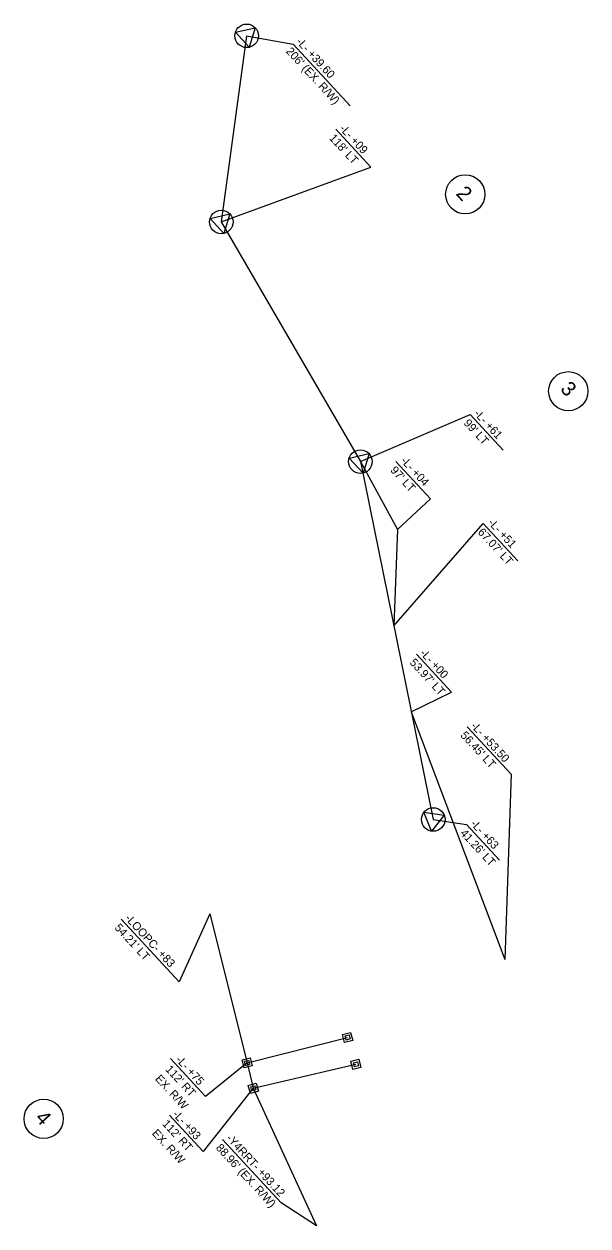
# Model space of a CAD drawing. Extents: x 1703100 to 1704058, y 794243 to 795715.
# Drawn here: x 1703714 to 1704058, y 794243 to 794978 of the extents above; entities that cross this region are included whole.
import ezdxf

# ---------------------------------------------------------------- set-up
doc = ezdxf.new("R2010")
doc.units = 0
for name, color, linetype in [('Prop Easement Construction', 7, 'Continuous'), ('Prop Easement Construction Station Offsets', 7, 'Continuous'), ('Prop Easement Permanent Drainage', 7, 'Continuous'), ('Prop Easement Permanent Drainage Station Offsets', 7, 'Continuous'), ('Prop Easement Temporary Drainage', 7, 'Continuous'), ('Prop Easement Temporary Drainage Station Offsets', 7, 'Continuous'), ('Prop Parcel Number CELL', 7, 'Continuous'), ('Prop Parcel Number Text', 7, 'Continuous'), ('Prop ROW Marker CELL', 7, 'Continuous'), ('Prop ROW Permanent Easement CELL', 7, 'Continuous'), ('Prop ROW RW Lines', 7, 'Continuous'), ('Prop ROW Station Offsets', 7, 'Continuous')]:
    doc.layers.add(name, color=color, linetype=linetype)

msp = doc.modelspace()

# ---------------------------------------------------------------- linework, layer by layer
at = {"layer": 'Prop Easement Construction'}
for p, q in [((1703950.31, 794557.04), (1704007.51, 794405.65)), ((1703827.17, 794433.6), (1703850, 794342.38)), ((1703853.78, 794326.85), (1703892.47, 794242.67))]:
    msp.add_line(p, q, dxfattribs=at)
at = {"layer": 'Prop Easement Construction Station Offsets'}
for p, q in [((1703953.44, 794592.3), (1703974.97, 794568.98)), ((1703950.31, 794557.04), (1703974.97, 794568.98)), ((1703984.48, 794547.84), (1704011.25, 794518.83)), ((1704011.25, 794518.83), (1704007.51, 794405.65)), ((1703827.17, 794433.6), (1703808.47, 794391.95)), ((1703773.14, 794430.21), (1703808.47, 794391.95)), ((1703835.01, 794295.6), (1703870.79, 794256.84)), ((1703892.47, 794242.67), (1703870.79, 794256.84))]:
    msp.add_line(p, q, dxfattribs=at)
at = {"layer": 'Prop Easement Permanent Drainage'}
for p, q in [((1703850, 794342.38), (1703911.4, 794357.91)), ((1703850, 794342.38), (1703853.78, 794326.85)), ((1703853.78, 794326.85), (1703916.46, 794341.51))]:
    msp.add_line(p, q, dxfattribs=at)
at = {"layer": 'Prop Easement Permanent Drainage Station Offsets'}
for p, q in [((1703803.25, 794345), (1703824.56, 794321.92)), ((1703850, 794342.38), (1703824.56, 794321.92)), ((1703853.78, 794326.85), (1703823.09, 794288.17)), ((1703802.49, 794310.49), (1703823.09, 794288.17))]:
    msp.add_line(p, q, dxfattribs=at)
at = {"layer": 'Prop Easement Temporary Drainage'}
for p, q in [((1703919.23, 794710.03), (1703941.8, 794668.51)), ((1703941.8, 794668.51), (1703939.64, 794609.55))]:
    msp.add_line(p, q, dxfattribs=at)
at = {"layer": 'Prop Easement Temporary Drainage Station Offsets'}
for p, q in [((1703962.01, 794687.16), (1703940.79, 794710.15)), ((1703941.8, 794668.51), (1703962.01, 794687.16)), ((1703939.64, 794609.55), (1703994.15, 794672.27)), ((1704015.37, 794649.28), (1703994.15, 794672.27))]:
    msp.add_line(p, q, dxfattribs=at)
at = {"layer": 'Prop Parcel Number CELL'}
for p, q in [((1703983.3, 794873.43), (1703983.3, 794873.43)), ((1704046.26, 794753.04), (1704046.26, 794753.04)), ((1703725.7, 794308.16), (1703725.7, 794308.16))]:
    msp.add_line(p, q, dxfattribs=at)
for centre in [(1703983.3, 794873.43), (1704046.26, 794753.04), (1703725.7, 794308.16)]:
    msp.add_circle(centre, 12, dxfattribs=at)
at = {"layer": 'Prop ROW Marker CELL'}
for p, q in [((1703849.71, 794970.36), (1703849.71, 794970.36)), ((1703834.24, 794856.55), (1703834.24, 794856.55)), ((1703919.23, 794710.03), (1703919.23, 794710.03)), ((1703963.72, 794491.19), (1703963.72, 794491.19))]:
    msp.add_line(p, q, dxfattribs=at)
for points in [[(1703842.82, 794972.51), (1703855, 794975.24), (1703851.3, 794963.32)], [(1703827.35, 794858.7), (1703839.53, 794861.43), (1703835.83, 794849.52)], [(1703912.35, 794712.18), (1703924.52, 794714.91), (1703920.83, 794702.99)], [(1703958.06, 794495.65), (1703970.4, 794493.86), (1703962.7, 794484.05)]]:
    msp.add_lwpolyline(points, close=True, dxfattribs=at)
for centre in [(1703849.71, 794970.36), (1703834.24, 794856.55), (1703919.23, 794710.03), (1703963.72, 794491.19)]:
    msp.add_circle(centre, 7.2, dxfattribs=at)
at = {"layer": 'Prop ROW Permanent Easement CELL'}
for p, q in [((1703911.41, 794357.91), (1703911.41, 794357.91)), ((1703850, 794342.38), (1703850, 794342.38)), ((1703916.46, 794341.51), (1703916.46, 794341.51)), ((1703853.78, 794326.85), (1703853.78, 794326.85))]:
    msp.add_line(p, q, dxfattribs=at)
for points in [[(1703914.51, 794356.09), (1703909.58, 794354.81), (1703908.3, 794359.74), (1703913.23, 794361.02)], [(1703912.96, 794357), (1703910.49, 794356.36), (1703909.85, 794358.83), (1703912.32, 794359.47)], [(1703851.89, 794345.45), (1703853.06, 794340.49), (1703848.11, 794339.32), (1703846.94, 794344.27)], [(1703850.95, 794343.92), (1703851.53, 794341.44), (1703849.06, 794340.85), (1703848.47, 794343.33)], [(1703919.55, 794339.66), (1703914.61, 794338.42), (1703913.37, 794343.36), (1703918.3, 794344.6)], [(1703918, 794340.59), (1703915.53, 794339.97), (1703914.91, 794342.43), (1703917.38, 794343.05)], [(1703850.64, 794328.62), (1703855.55, 794329.99), (1703856.92, 794325.09), (1703852.02, 794323.72)], [(1703852.21, 794327.74), (1703854.66, 794328.42), (1703855.35, 794325.97), (1703852.9, 794325.28)]]:
    msp.add_lwpolyline(points, close=True, dxfattribs=at)
at = {"layer": 'Prop ROW RW Lines'}
for points in [[(1703849.71, 794970.36), (1703834.24, 794856.55)], [(1703834.24, 794856.55), (1703919.23, 794710.03)], [(1703919.23, 794710.03), (1703963.72, 794491.19)]]:
    msp.add_lwpolyline(points, dxfattribs=at)
at = {"layer": 'Prop ROW Station Offsets'}
for p, q in [((1703849.71, 794970.36), (1703878.04, 794965.3)), ((1703878.04, 794965.3), (1703912.93, 794927.51)), ((1703925.62, 794890.03), (1703904.14, 794913.3)), ((1703834.24, 794856.55), (1703925.62, 794890.03)), ((1703919.23, 794710.03), (1703986.25, 794738.84)), ((1703986.25, 794738.84), (1704006.37, 794717.04)), ((1703963.72, 794491.19), (1703984.09, 794488.09)), ((1703984.09, 794488.09), (1704004.21, 794466.29))]:
    msp.add_line(p, q, dxfattribs=at)

# ---------------------------------------------------------------- texts
at = {"layer": 'Prop Easement Construction Station Offsets'}
for s, p in [("53.97' LT  ", (1703948.98, 794586.83)), ('-L- +00', (1703955.28, 794592.64)), ("56.45' LT  ", (1703980.02, 794542.36)), ('-L- +53.50', (1703986.32, 794548.18)), ("54.21' LT  ", (1703768.69, 794424.74)), ('-LOOPC- +83', (1703774.99, 794430.55)), ('-Y4RRT- +93.12', (1703836.86, 794295.94)), ("88.96' (EX. R/W) ", (1703830.56, 794290.13))]:
    msp.add_text(s, height=5, rotation=312.70907, dxfattribs=at).set_placement(p)
at = {"layer": 'Prop Easement Permanent Drainage Station Offsets'}
for s, p in [('-L- +75', (1703806.04, 794343.97)), ("112' RT", (1703799.75, 794338.15)), ('EX. R/W', (1703793.45, 794332.34)), ('-L- +93', (1703804.12, 794310.64)), ('EX. R/W', (1703791.53, 794299.02)), ("112' RT", (1703797.83, 794304.83))]:
    msp.add_text(s, height=5, rotation=312.70907, dxfattribs=at).set_placement(p)
at = {"layer": 'Prop Easement Temporary Drainage Station Offsets'}
for s, p in [("97' LT", (1703937.22, 794704.44)), ('-L- +04', (1703943.52, 794710.26)), ("67.07' LT", (1703990.58, 794666.56)), ('-L- +51', (1703996.88, 794672.37))]:
    msp.add_text(s, height=5, rotation=312.70907, dxfattribs=at).set_placement(p)
at = {"layer": 'Prop Parcel Number Text'}
for s, p in [('2', (1703977.18, 794873.52)), ('3', (1704040.92, 794754.01)), ('4', (1703720.01, 794308.28))]:
    msp.add_text(s, height=9, rotation=312.70907, dxfattribs=at).set_placement(p)
at = {"layer": 'Prop ROW Station Offsets'}
for s, p in [("206' (EX. R/W)", (1703873.38, 794960.6)), ('-L- +39.60', (1703879.67, 794966.41)), ('-L- +09', (1703906.11, 794913.37)), ("118' LT", (1703899.81, 794907.56)), ("99' LT", (1703982.02, 794733.23)), ('-L- +61', (1703988.32, 794739.05)), ('-L- +63', (1703986.16, 794488.3)), ("41.26' LT", (1703979.87, 794482.48))]:
    msp.add_text(s, height=5, rotation=312.70907, dxfattribs=at).set_placement(p)

doc.saveas('drawing.dxf')
